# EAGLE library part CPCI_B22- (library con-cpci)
Compact PCI B 22 Source: www.erni.com
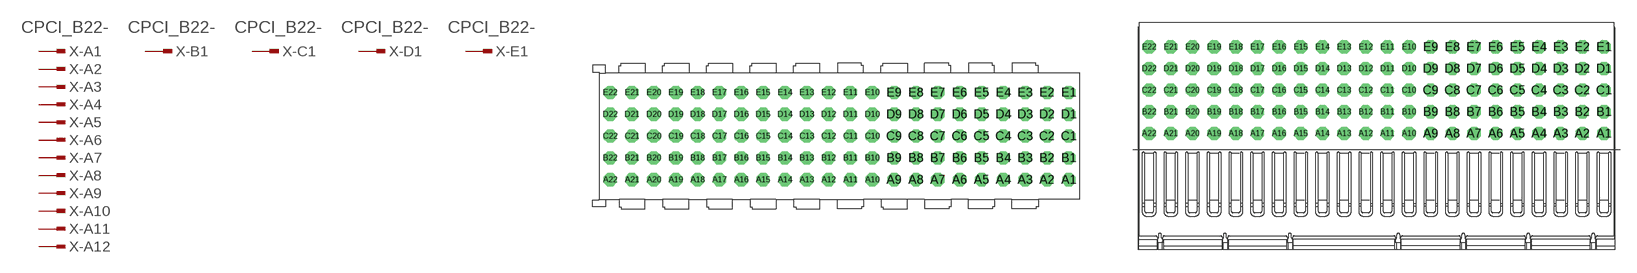
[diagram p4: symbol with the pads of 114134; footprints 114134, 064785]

Designator prefix X; gates -A1=PINV -B1=PINV -C1=PINV -D1=PINV -E1=PINV -A2=PIN -A3=PIN -A4=PIN -A5=PIN -A6=PIN -A7=PIN -A8=PIN -A9=PIN -A10=PIN -A11=PIN -A12=PIN -A13=PIN -A14=PIN -A15=PIN -A16=PIN -A17=PIN -A18=PIN -A19=PIN -A20=PIN -A21=PIN -A22=PIN -B2=PIN -B3=PIN -B4=PIN -B5=PIN -B6=PIN -B7=PIN -B8=PIN -B9=PIN -B10=PIN -B11=PIN -B12=PIN -B13=PIN -B14=PIN -B15=PIN -B16=PIN -B17=PIN -B18=PIN -B19=PIN -B20=PIN -B21=PIN -B22=PIN -C2=PIN -C3=PIN -C4=PIN -C5=PIN -C6=PIN -C7=PIN -C8=PIN -C9=PIN -C10=PIN -C11=PIN -C12=PIN -C13=PIN -C14=PIN -C15=PIN -C16=PIN -C17=PIN -C18=PIN -C19=PIN -C20=PIN -C21=PIN -C22=PIN -D2=PIN -D3=PIN -D4=PIN -D5=PIN -D6=PIN -D7=PIN -D8=PIN -D9=PIN -D10=PIN -D11=PIN -D12=PIN -D13=PIN -D14=PIN -D15=PIN -D16=PIN -D17=PIN -D18=PIN -D19=PIN -D20=PIN -D21=PIN -D22=PIN -E2=PIN -E3=PIN -E4=PIN -E5=PIN -E6=PIN -E7=PIN -E8=PIN -E9=PIN -E10=PIN -E11=PIN -E12=PIN -E13=PIN -E14=PIN -E15=PIN -E16=PIN -E17=PIN -E18=PIN -E19=PIN -E20=PIN -E21=PIN -E22=PIN

## CPCI_B22-114134  [114134]
A1  -A1:1  in
A2  -A2:1  in
A3  -A3:1  in
A4  -A4:1  in
A5  -A5:1  in
A6  -A6:1  in
A7  -A7:1  in
A8  -A8:1  in
A9  -A9:1  in
A10  -A10:1  in
A11  -A11:1  in
A12  -A12:1  in
A13  -A13:1  in
A14  -A14:1  in
A15  -A15:1  in
A16  -A16:1  in
A17  -A17:1  in
A18  -A18:1  in
A19  -A19:1  in
A20  -A20:1  in
A21  -A21:1  in
A22  -A22:1  in
B1  -B1:1  in
B2  -B2:1  in
B3  -B3:1  in
B4  -B4:1  in
B5  -B5:1  in
B6  -B6:1  in
B7  -B7:1  in
B8  -B8:1  in
B9  -B9:1  in
B10  -B10:1  in
B11  -B11:1  in
B12  -B12:1  in
B13  -B13:1  in
B14  -B14:1  in
B15  -B15:1  in
B16  -B16:1  in
B17  -B17:1  in
B18  -B18:1  in
B19  -B19:1  in
B20  -B20:1  in
B21  -B21:1  in
B22  -B22:1  in
C1  -C1:1  in
C2  -C2:1  in
C3  -C3:1  in
C4  -C4:1  in
C5  -C5:1  in
C6  -C6:1  in
C7  -C7:1  in
C8  -C8:1  in
C9  -C9:1  in
C10  -C10:1  in
C11  -C11:1  in
C12  -C12:1  in
C13  -C13:1  in
C14  -C14:1  in
C15  -C15:1  in
C16  -C16:1  in
C17  -C17:1  in
C18  -C18:1  in
C19  -C19:1  in
C20  -C20:1  in
C21  -C21:1  in
C22  -C22:1  in
D1  -D1:1  in
D2  -D2:1  in
D3  -D3:1  in
D4  -D4:1  in
D5  -D5:1  in
D6  -D6:1  in
D7  -D7:1  in
D8  -D8:1  in
D9  -D9:1  in
D10  -D10:1  in
D11  -D11:1  in
D12  -D12:1  in
D13  -D13:1  in
D14  -D14:1  in
D15  -D15:1  in
D16  -D16:1  in
D17  -D17:1  in
D18  -D18:1  in
D19  -D19:1  in
D20  -D20:1  in
D21  -D21:1  in
D22  -D22:1  in
E1  -E1:1  in
E2  -E2:1  in
E3  -E3:1  in
E4  -E4:1  in
E5  -E5:1  in
E6  -E6:1  in
E7  -E7:1  in
E8  -E8:1  in
E9  -E9:1  in
E10  -E10:1  in
E11  -E11:1  in
E12  -E12:1  in
E13  -E13:1  in
E14  -E14:1  in
E15  -E15:1  in
E16  -E16:1  in
E17  -E17:1  in
E18  -E18:1  in
E19  -E19:1  in
E20  -E20:1  in
E21  -E21:1  in
E22  -E22:1  in

## CPCI_B22-064785  [064785]
Pads as for 114134

## CPCI_B22-914797I  [914797I]
Pads as for 114134

## Footprint 114134 (pad centres in mm)
ERmet-FS Federleiste B22 / ERmet-Female Straight Type B22 Source: http://www.erni.com/DB/PDF-Drawing/ERmet/114134.pdf
drill 0.7 pad 1.016 octagon: A1 21,-5; A2 19,-5; A3 17,-5; A4 15,-5; A5 13,-5; A6 11,-5; A7 9,-5; A8 7,-5; A9 5,-5; A10 3,-5; A11 1,-5; A12 -1,-5; A13 -3,-5; A14 -5,-5; A15 -7,-5; A16 -9,-5; A17 -11,-5; A18 -13,-5; A19 -15,-5; A20 -17,-5; A21 -19,-5; A22 -21,-5; B1 21,-3; B2 19,-3; B3 17,-3; B4 15,-3; B5 13,-3; B6 11,-3; B7 9,-3; B8 7,-3; B9 5,-3; B10 3,-3; B11 1,-3; B12 -1,-3; B13 -3,-3; B14 -5,-3; B15 -7,-3; B16 -9,-3; B17 -11,-3; B18 -13,-3; B19 -15,-3; B20 -17,-3; B21 -19,-3; B22 -21,-3; C1 21,-1; C2 19,-1; C3 17,-1; C4 15,-1; C5 13,-1; C6 11,-1; C7 9,-1; C8 7,-1; C9 5,-1; C10 3,-1; C11 1,-1; C12 -1,-1; C13 -3,-1; C14 -5,-1; C15 -7,-1; C16 -9,-1; C17 -11,-1; C18 -13,-1; C19 -15,-1; C20 -17,-1; C21 -19,-1; C22 -21,-1; D1 21,1; D2 19,1; D3 17,1; D4 15,1; D5 13,1; D6 11,1; D7 9,1; D8 7,1; D9 5,1; D10 3,1; D11 1,1; D12 -1,1; D13 -3,1; D14 -5,1; D15 -7,1; D16 -9,1; D17 -11,1; D18 -13,1; D19 -15,1; D20 -17,1; D21 -19,1; D22 -21,1; E1 21,3; E2 19,3; E3 17,3; E4 15,3; E5 13,3; E6 11,3; E7 9,3; E8 7,3; E9 5,3; E10 3,3; E11 1,3; E12 -1,3; E13 -3,3; E14 -5,3; E15 -7,3; E16 -9,3; E17 -11,3; E18 -13,3; E19 -15,3; E20 -17,3; E21 -19,3; E22 -21,3

## Footprint 064785 (pad centres in mm)
ERmet Federleiste B 22 / ERmet Female Type B 22 Source: http://www.erni.com/DB/PDF-Drawing/ERmet/064785.pdf
drill 0.7 pad 1.016 octagon: A1 21,1.5; A2 19,1.5; A3 17,1.5; A4 15,1.5; A5 13,1.5; A6 11,1.5; A7 9,1.5; A8 7,1.5; A9 5,1.5; A10 3,1.5; A11 1,1.5; A12 -1,1.5; A13 -3,1.5; A14 -5,1.5; A15 -7,1.5; A16 -9,1.5; A17 -11,1.5; A18 -13,1.5; A19 -15,1.5; A20 -17,1.5; A21 -19,1.5; A22 -21,1.5; B1 21,3.5; B2 19,3.5; B3 17,3.5; B4 15,3.5; B5 13,3.5; B6 11,3.5; B7 9,3.5; B8 7,3.5; B9 5,3.5; B10 3,3.5; B11 1,3.5; B12 -1,3.5; B13 -3,3.5; B14 -5,3.5; B15 -7,3.5; B16 -9,3.5; B17 -11,3.5; B18 -13,3.5; B19 -15,3.5; B20 -17,3.5; B21 -19,3.5; B22 -21,3.5; C1 21,5.5; C2 19,5.5; C3 17,5.5; C4 15,5.5; C5 13,5.5; C6 11,5.5; C7 9,5.5; C8 7,5.5; C9 5,5.5; C10 3,5.5; C11 1,5.5; C12 -1,5.5; C13 -3,5.5; C14 -5,5.5; C15 -7,5.5; C16 -9,5.5; C17 -11,5.5; C18 -13,5.5; C19 -15,5.5; C20 -17,5.5; C21 -19,5.5; C22 -21,5.5; D1 21,7.5; D2 19,7.5; D3 17,7.5; D4 15,7.5; D5 13,7.5; D6 11,7.5; D7 9,7.5; D8 7,7.5; D9 5,7.5; D10 3,7.5; D11 1,7.5; D12 -1,7.5; D13 -3,7.5; D14 -5,7.5; D15 -7,7.5; D16 -9,7.5; D17 -11,7.5; D18 -13,7.5; D19 -15,7.5; D20 -17,7.5; D21 -19,7.5; D22 -21,7.5; E1 21,9.5; E2 19,9.5; E3 17,9.5; E4 15,9.5; E5 13,9.5; E6 11,9.5; E7 9,9.5; E8 7,9.5; E9 5,9.5; E10 3,9.5; E11 1,9.5; E12 -1,9.5; E13 -3,9.5; E14 -5,9.5; E15 -7,9.5; E16 -9,9.5; E17 -11,9.5; E18 -13,9.5; E19 -15,9.5; E20 -17,9.5; E21 -19,9.5; E22 -21,9.5

## Footprint 914797I (pad centres in mm)
ERmet Federleiste B 22 / ERmet Female Type B 22 Source: http://www.erni.com/DB/PDF-Drawing/ERmet/914797i.pdf
drill 0.7 pad 1.016 octagon: A1 11,-64; A2 9,-64; A3 7,-64; A4 5,-64; A5 3,-64; A6 1,-64; A7 -1,-64; A8 -3,-64; A9 -5,-64; A10 -7,-64; A11 -9,-64; A12 -11,-64; A13 -13,-64; A14 -15,-64; A15 -17,-64; A16 -19,-64; A17 -21,-64; A18 -23,-64; A19 -25,-64; A20 -27,-64; A21 -29,-64; A22 -31,-64; B1 11,-62; B2 9,-62; B3 7,-62; B4 5,-62; B5 3,-62; B6 1,-62; B7 -1,-62; B8 -3,-62; B9 -5,-62; B10 -7,-62; B11 -9,-62; B12 -11,-62; B13 -13,-62; B14 -15,-62; B15 -17,-62; B16 -19,-62; B17 -21,-62; B18 -23,-62; B19 -25,-62; B20 -27,-62; B21 -29,-62; B22 -31,-62; C1 11,-60; C2 9,-60; C3 7,-60; C4 5,-60; C5 3,-60; C6 1,-60; C7 -1,-60; C8 -3,-60; C9 -5,-60; C10 -7,-60; C11 -9,-60; C12 -11,-60; C13 -13,-60; C14 -15,-60; C15 -17,-60; C16 -19,-60; C17 -21,-60; C18 -23,-60; C19 -25,-60; C20 -27,-60; C21 -29,-60; C22 -31,-60; D1 11,-58; D2 9,-58; D3 7,-58; D4 5,-58; D5 3,-58; D6 1,-58; D7 -1,-58; D8 -3,-58; D9 -5,-58; D10 -7,-58; D11 -9,-58; D12 -11,-58; D13 -13,-58; D14 -15,-58; D15 -17,-58; D16 -19,-58; D17 -21,-58; D18 -23,-58; D19 -25,-58; D20 -27,-58; D21 -29,-58; D22 -31,-58; E1 11,-56; E2 9,-56; E3 7,-56; E4 5,-56; E5 3,-56; E6 1,-56; E7 -1,-56; E8 -3,-56; E9 -5,-56; E10 -7,-56; E11 -9,-56; E12 -11,-56; E13 -13,-56; E14 -15,-56; E15 -17,-56; E16 -19,-56; E17 -21,-56; E18 -23,-56; E19 -25,-56; E20 -27,-56; E21 -29,-56; E22 -31,-56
